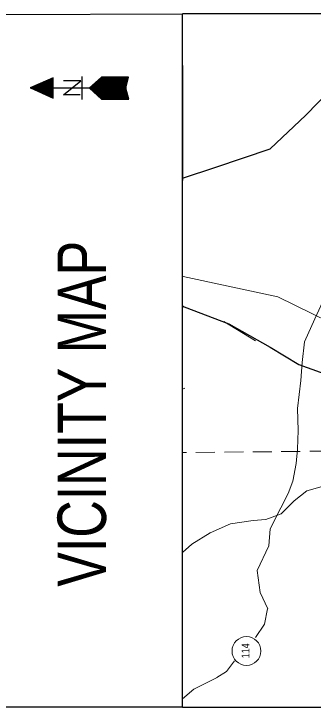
# Model space of a CAD drawing. Extents: x 2363323 to 2367082, y 6956018 to 6980837.
# Drawn here: x 2365644.7 to 2365838.7, y 6980386 to 6980835.5 of the extents above; entities that cross this region are included whole.
import ezdxf

# ---------------------------------------------------------------- set-up
doc = ezdxf.new("R2010")
doc.units = 0
doc.header["$LTSCALE"] = 4.1
doc.linetypes.add('MEDIUM_DASHED', pattern=[4.5, 3, -1.5])
doc.layers.add('62', color=7, linetype='Continuous', lineweight=13)
doc.layers.add('63', color=7, linetype='Continuous', lineweight=13)

msp = doc.modelspace()

# ---------------------------------------------------------------- linework, layer by layer
at = {"layer": '62', "lineweight": 25}
for p, q in [((2365753.976, 6980385.954), (2365753.974, 6980835.546)), ((2365688.99, 6980779.92), (2365688.99, 6980794.863)), ((2365655.17, 6980787.596), (2365717.68, 6980787.594))]:
    msp.add_line(p, q, dxfattribs=at)
at = {"layer": '62'}
for p, q in [((2365754.2, 6980727.402), (2365754.2, 6980802.018)), ((2365666.622, 6980782.485), (2365666.622, 6980792.566)), ((2365667.25, 6980782.192), (2365667.252, 6980792.836)), ((2365670.086, 6980792.859), (2365667.318, 6980792.859)), ((2365667.858, 6980781.902), (2365667.858, 6980793.108)), ((2365668.51, 6980781.63), (2365668.51, 6980793.399)), ((2365670.086, 6980793.512), (2365668.758, 6980793.512)), ((2365669.142, 6980781.338), (2365669.14, 6980793.67)), ((2365669.75, 6980781.045), (2365669.748, 6980793.939)), ((2365699.316, 6980782.282), (2365699.316, 6980792.522)), ((2365718.555, 6980792.859), (2365699.721, 6980792.859)), ((2365699.946, 6980781.72), (2365699.946, 6980793.084)), ((2365718.692, 6980793.512), (2365700.441, 6980793.512)), ((2365700.598, 6980781.136), (2365700.598, 6980793.622)), ((2365718.826, 6980794.119), (2365701.138, 6980794.119)), ((2365701.208, 6980780.595), (2365701.206, 6980794.186)), ((2365701.838, 6980780.258), (2365701.836, 6980794.503)), ((2365702.466, 6980780.258), (2365702.466, 6980794.503)), ((2365703.096, 6980780.258), (2365703.096, 6980794.502)), ((2365703.729, 6980780.258), (2365703.728, 6980794.502)), ((2365704.358, 6980780.258), (2365704.359, 6980794.502)), ((2365704.99, 6980780.258), (2365704.989, 6980794.503)), ((2365705.62, 6980780.258), (2365705.619, 6980794.502)), ((2365706.249, 6980780.258), (2365706.25, 6980794.502)), ((2365706.879, 6980780.256), (2365706.879, 6980794.502)), ((2365707.51, 6980780.256), (2365707.509, 6980794.5)), ((2365708.139, 6980780.259), (2365708.14, 6980794.502)), ((2365708.746, 6980780.259), (2365708.748, 6980794.502)), ((2365709.399, 6980780.258), (2365709.399, 6980794.503)), ((2365710.029, 6980780.258), (2365710.029, 6980794.502)), ((2365710.638, 6980780.259), (2365710.636, 6980794.503)), ((2365711.289, 6980780.258), (2365711.289, 6980794.502)), ((2365711.896, 6980780.258), (2365711.896, 6980794.503)), ((2365712.528, 6980780.258), (2365712.526, 6980794.502)), ((2365713.179, 6980780.258), (2365713.179, 6980794.502)), ((2365713.786, 6980780.258), (2365713.786, 6980794.502)), ((2365714.418, 6980780.258), (2365714.416, 6980794.502)), ((2365715.046, 6980780.259), (2365715.048, 6980794.502)), ((2365715.676, 6980780.258), (2365715.676, 6980794.503)), ((2365716.308, 6980780.258), (2365716.306, 6980794.502)), ((2365716.938, 6980780.258), (2365716.936, 6980794.502)), ((2365717.566, 6980788.336), (2365717.566, 6980794.502)), ((2365718.196, 6980791.24), (2365718.198, 6980794.503)), ((2365718.826, 6980794.096), (2365718.828, 6980794.502)), ((2365656.563, 6980787.1), (2365656.564, 6980788.134)), ((2365657.17, 6980786.806), (2365657.172, 6980788.426)), ((2365670.084, 6980788.472), (2365657.307, 6980788.472)), ((2365657.824, 6980786.514), (2365657.823, 6980788.698)), ((2365658.432, 6980786.22), (2365658.432, 6980788.965)), ((2365670.087, 6980789.08), (2365658.746, 6980789.079)), ((2365659.06, 6980785.95), (2365659.06, 6980789.238)), ((2365659.714, 6980785.658), (2365659.712, 6980789.506)), ((2365670.086, 6980789.732), (2365660.163, 6980789.732)), ((2365660.322, 6980785.365), (2365660.32, 6980789.776)), ((2365660.95, 6980785.072), (2365660.95, 6980790.069)), ((2365661.582, 6980784.78), (2365661.58, 6980790.339)), ((2365670.086, 6980790.362), (2365661.603, 6980790.362)), ((2365662.212, 6980784.488), (2365662.21, 6980790.632)), ((2365662.84, 6980784.218), (2365662.84, 6980790.902)), ((2365670.087, 6980790.968), (2365663.02, 6980790.97)), ((2365663.47, 6980783.926), (2365663.47, 6980791.194)), ((2365664.1, 6980783.634), (2365664.1, 6980791.464)), ((2365670.087, 6980791.622), (2365664.462, 6980791.622)), ((2365664.73, 6980783.362), (2365664.73, 6980791.734)), ((2365665.362, 6980783.048), (2365665.36, 6980792.004)), ((2365670.086, 6980792.229), (2365665.9, 6980792.23)), ((2365665.992, 6980782.755), (2365665.99, 6980792.274)), ((2365694.3, 6980786.829), (2365694.298, 6980788.089)), ((2365717.589, 6980788.472), (2365694.728, 6980788.472)), ((2365694.928, 6980786.265), (2365694.93, 6980788.652)), ((2365717.726, 6980789.079), (2365695.446, 6980789.079)), ((2365695.56, 6980785.704), (2365695.558, 6980789.192)), ((2365717.882, 6980789.733), (2365696.144, 6980789.732)), ((2365696.168, 6980785.14), (2365696.166, 6980789.754)), ((2365696.818, 6980784.555), (2365696.818, 6980790.294)), ((2365717.994, 6980790.363), (2365696.864, 6980790.362)), ((2365697.45, 6980783.994), (2365697.448, 6980790.856)), ((2365718.153, 6980790.969), (2365697.561, 6980790.969)), ((2365698.056, 6980783.43), (2365698.058, 6980791.42)), ((2365718.286, 6980791.62), (2365698.281, 6980791.622)), ((2365698.708, 6980782.868), (2365698.71, 6980791.959)), ((2365718.422, 6980792.229), (2365699.001, 6980792.229)), ((2365670.087, 6980787.842), (2365655.867, 6980787.842)), ((2365655.933, 6980787.392), (2365655.934, 6980787.864)), ((2365670.087, 6980787.212), (2365656.317, 6980787.212)), ((2365670.087, 6980786.583), (2365657.667, 6980786.582)), ((2365670.086, 6980785.95), (2365659.06, 6980785.95)), ((2365670.086, 6980785.32), (2365660.412, 6980785.32)), ((2365670.087, 6980784.69), (2365661.784, 6980784.69)), ((2365670.087, 6980784.06), (2365663.178, 6980784.06)), ((2365717.432, 6980787.212), (2365693.872, 6980787.212)), ((2365717.454, 6980787.842), (2365694.006, 6980787.842)), ((2365717.59, 6980786.583), (2365694.568, 6980786.583)), ((2365717.724, 6980785.95), (2365695.266, 6980785.948)), ((2365717.883, 6980785.322), (2365695.964, 6980785.32)), ((2365718.04, 6980784.69), (2365696.661, 6980784.69)), ((2365718.198, 6980784.06), (2365697.358, 6980784.06)), ((2365717.566, 6980780.256), (2365717.566, 6980786.649)), ((2365718.198, 6980780.258), (2365718.198, 6980784.06)), ((2365670.086, 6980783.43), (2365664.528, 6980783.43)), ((2365670.086, 6980782.802), (2365665.923, 6980782.8)), ((2365670.086, 6980782.17), (2365667.274, 6980782.172)), ((2365670.086, 6980781.54), (2365668.67, 6980781.542)), ((2365670.086, 6980780.932), (2365670.018, 6980780.932)), ((2365718.356, 6980783.43), (2365698.056, 6980783.43)), ((2365718.49, 6980782.8), (2365698.755, 6980782.8)), ((2365718.648, 6980782.17), (2365699.451, 6980782.168)), ((2365718.804, 6980781.542), (2365700.15, 6980781.54)), ((2365718.963, 6980780.932), (2365700.846, 6980780.932)), ((2365719.119, 6980780.282), (2365701.544, 6980780.28)), ((2365718.826, 6980780.259), (2365718.828, 6980781.472)), ((2365801.432, 6980623.464), (2365780.865, 6980636.09)), ((2365753.976, 6980592.164), (2365755.55, 6980592.862)), ((2365809.15, 6980449.68), (2365807.103, 6980439.848)), ((2365807.103, 6980439.848), (2365801.296, 6980431.162)), ((2365782.575, 6980408.974), (2365787.682, 6980416.04)), ((2365776.365, 6980405.082), (2365782.575, 6980408.974))]:
    msp.add_line(p, q, dxfattribs=at)
at = {"layer": '62', "linetype": 'MEDIUM_DASHED'}
msp.add_line((2365848.822, 6980551.996), (2365753.976, 6980551.008), dxfattribs=at)
at = {"layer": '62', "lineweight": 25}
for points in [[(2365753.976, 6980385.954), (2365634.174, 6980385.956), (2365634.172, 6980835.21), (2365753.974, 6980835.546)], [(2365753.976, 6980385.954), (2366219.249, 6980385.954), (2366219.249, 6980835.546), (2365753.974, 6980835.546)], [(2365655.46, 6980787.592), (2365670.086, 6980780.888), (2365670.086, 6980794.096), (2365655.326, 6980787.594)], [(2365693.692, 6980787.392), (2365701.568, 6980780.258), (2365719.119, 6980780.258), (2365717.364, 6980787.459), (2365718.916, 6980794.503), (2365701.568, 6980794.502), (2365693.736, 6980787.594)], [(2365753.976, 6980728.911), (2365775.622, 6980736.2), (2365810.86, 6980748.104), (2365833.947, 6980769.772), (2365857.058, 6980793.579), (2365861.646, 6980795.718)], [(2365687.752, 6980782.958), (2365676.75, 6980782.958), (2365688.156, 6980792.094), (2365676.748, 6980792.094)], [(2365753.974, 6980646.213), (2365755.146, 6980645.47), (2365784.062, 6980634.536), (2365810.86, 6980619.3), (2365829.356, 6980608.095), (2365860.208, 6980597.16)]]:
    msp.add_lwpolyline(points, dxfattribs=at)
at = {"layer": '62'}
for points in [[(2365809.287, 6980449.612), (2365804.356, 6980460.212), (2365802.512, 6980474.5), (2365809.894, 6980490.59), (2365810.838, 6980501.526), (2365817.837, 6980515.14), (2365822.54, 6980524.522), (2365825.554, 6980532.603), (2365827.714, 6980543.964), (2365828.59, 6980553.189), (2365829.04, 6980565.342), (2365828.5, 6980579.562), (2365830.796, 6980597.678), (2365831.606, 6980609.468), (2365833.203, 6980622.902), (2365839.778, 6980637.732), (2365846.368, 6980651.814), (2365853.028, 6980664.688), (2365864.278, 6980679.314), (2365871.414, 6980689.148), (2365878.929, 6980701.188), (2365885.793, 6980708.072)], [(2365871.414, 6980624.792), (2365815.923, 6980652.02), (2365754.402, 6980665.14)], [(2365753.974, 6980486.178), (2365760.05, 6980491.737), (2365771.955, 6980498.895), (2365785.095, 6980504.764), (2365799.742, 6980507.016), (2365808.048, 6980507.691), (2365817.97, 6980511.358), (2365826.498, 6980519.638), (2365834.6, 6980526.3), (2365844.567, 6980529.112), (2365856.966, 6980531.656)], [(2365753.976, 6980391.378), (2365761.377, 6980397.591), (2365776.545, 6980405.262)]]:
    msp.add_lwpolyline(points, dxfattribs=at)
msp.add_circle((2365795.467, 6980422.352), 9.364, dxfattribs=at)
at = {"layer": '63', "lineweight": 25}
for p, q in [((2365753.976, 6980385.954), (2365753.974, 6980835.546)), ((2365688.99, 6980779.92), (2365688.99, 6980794.863)), ((2365655.17, 6980787.596), (2365717.68, 6980787.594))]:
    msp.add_line(p, q, dxfattribs=at)
at = {"layer": '63'}
for p, q in [((2365754.2, 6980727.402), (2365754.2, 6980802.018)), ((2365666.622, 6980782.485), (2365666.622, 6980792.566)), ((2365667.25, 6980782.192), (2365667.252, 6980792.836)), ((2365670.086, 6980792.859), (2365667.318, 6980792.859)), ((2365667.858, 6980781.902), (2365667.858, 6980793.108)), ((2365668.51, 6980781.63), (2365668.51, 6980793.399)), ((2365670.086, 6980793.512), (2365668.758, 6980793.512)), ((2365669.142, 6980781.338), (2365669.14, 6980793.67)), ((2365669.75, 6980781.045), (2365669.748, 6980793.939)), ((2365699.316, 6980782.282), (2365699.316, 6980792.522)), ((2365718.555, 6980792.859), (2365699.721, 6980792.859)), ((2365699.946, 6980781.72), (2365699.946, 6980793.084)), ((2365718.692, 6980793.512), (2365700.441, 6980793.512)), ((2365700.598, 6980781.136), (2365700.598, 6980793.622)), ((2365718.826, 6980794.119), (2365701.138, 6980794.119)), ((2365701.208, 6980780.595), (2365701.206, 6980794.186)), ((2365701.838, 6980780.258), (2365701.836, 6980794.503)), ((2365702.466, 6980780.258), (2365702.466, 6980794.503)), ((2365703.096, 6980780.258), (2365703.096, 6980794.502)), ((2365703.729, 6980780.258), (2365703.728, 6980794.502)), ((2365704.358, 6980780.258), (2365704.359, 6980794.502)), ((2365704.99, 6980780.258), (2365704.989, 6980794.503)), ((2365705.62, 6980780.258), (2365705.619, 6980794.502)), ((2365706.249, 6980780.258), (2365706.25, 6980794.502)), ((2365706.879, 6980780.256), (2365706.879, 6980794.502)), ((2365707.51, 6980780.256), (2365707.509, 6980794.5)), ((2365708.139, 6980780.259), (2365708.14, 6980794.502)), ((2365708.746, 6980780.259), (2365708.748, 6980794.502)), ((2365709.399, 6980780.258), (2365709.399, 6980794.503)), ((2365710.029, 6980780.258), (2365710.029, 6980794.502)), ((2365710.638, 6980780.259), (2365710.636, 6980794.503)), ((2365711.289, 6980780.258), (2365711.289, 6980794.502)), ((2365711.896, 6980780.258), (2365711.896, 6980794.503)), ((2365712.528, 6980780.258), (2365712.526, 6980794.502)), ((2365713.179, 6980780.258), (2365713.179, 6980794.502)), ((2365713.786, 6980780.258), (2365713.786, 6980794.502)), ((2365714.418, 6980780.258), (2365714.416, 6980794.502)), ((2365715.046, 6980780.259), (2365715.048, 6980794.502)), ((2365715.676, 6980780.258), (2365715.676, 6980794.503)), ((2365716.308, 6980780.258), (2365716.306, 6980794.502)), ((2365716.938, 6980780.258), (2365716.936, 6980794.502)), ((2365717.566, 6980788.336), (2365717.566, 6980794.502)), ((2365718.196, 6980791.24), (2365718.198, 6980794.503)), ((2365718.826, 6980794.096), (2365718.828, 6980794.502)), ((2365656.563, 6980787.1), (2365656.564, 6980788.134)), ((2365657.17, 6980786.806), (2365657.172, 6980788.426)), ((2365670.084, 6980788.472), (2365657.307, 6980788.472)), ((2365657.824, 6980786.514), (2365657.823, 6980788.698)), ((2365658.432, 6980786.22), (2365658.432, 6980788.965)), ((2365670.087, 6980789.08), (2365658.746, 6980789.079)), ((2365659.06, 6980785.95), (2365659.06, 6980789.238)), ((2365659.714, 6980785.658), (2365659.712, 6980789.506)), ((2365670.086, 6980789.732), (2365660.163, 6980789.732)), ((2365660.322, 6980785.365), (2365660.32, 6980789.776)), ((2365660.95, 6980785.072), (2365660.95, 6980790.069)), ((2365661.582, 6980784.78), (2365661.58, 6980790.339)), ((2365670.086, 6980790.362), (2365661.603, 6980790.362)), ((2365662.212, 6980784.488), (2365662.21, 6980790.632)), ((2365662.84, 6980784.218), (2365662.84, 6980790.902)), ((2365670.087, 6980790.968), (2365663.02, 6980790.97)), ((2365663.47, 6980783.926), (2365663.47, 6980791.194)), ((2365664.1, 6980783.634), (2365664.1, 6980791.464)), ((2365670.087, 6980791.622), (2365664.462, 6980791.622)), ((2365664.73, 6980783.362), (2365664.73, 6980791.734)), ((2365665.362, 6980783.048), (2365665.36, 6980792.004)), ((2365670.086, 6980792.229), (2365665.9, 6980792.23)), ((2365665.992, 6980782.755), (2365665.99, 6980792.274)), ((2365694.3, 6980786.829), (2365694.298, 6980788.089)), ((2365717.589, 6980788.472), (2365694.728, 6980788.472)), ((2365694.928, 6980786.265), (2365694.93, 6980788.652)), ((2365717.726, 6980789.079), (2365695.446, 6980789.079)), ((2365695.56, 6980785.704), (2365695.558, 6980789.192)), ((2365717.882, 6980789.733), (2365696.144, 6980789.732)), ((2365696.168, 6980785.14), (2365696.166, 6980789.754)), ((2365696.818, 6980784.555), (2365696.818, 6980790.294)), ((2365717.994, 6980790.363), (2365696.864, 6980790.362)), ((2365697.45, 6980783.994), (2365697.448, 6980790.856)), ((2365718.153, 6980790.969), (2365697.561, 6980790.969)), ((2365698.056, 6980783.43), (2365698.058, 6980791.42)), ((2365718.286, 6980791.62), (2365698.281, 6980791.622)), ((2365698.708, 6980782.868), (2365698.71, 6980791.959)), ((2365718.422, 6980792.229), (2365699.001, 6980792.229)), ((2365670.087, 6980787.842), (2365655.867, 6980787.842)), ((2365655.933, 6980787.392), (2365655.934, 6980787.864)), ((2365670.087, 6980787.212), (2365656.317, 6980787.212)), ((2365670.087, 6980786.583), (2365657.667, 6980786.582)), ((2365670.086, 6980785.95), (2365659.06, 6980785.95)), ((2365670.086, 6980785.32), (2365660.412, 6980785.32)), ((2365670.087, 6980784.69), (2365661.784, 6980784.69)), ((2365670.087, 6980784.06), (2365663.178, 6980784.06)), ((2365717.432, 6980787.212), (2365693.872, 6980787.212)), ((2365717.454, 6980787.842), (2365694.006, 6980787.842)), ((2365717.59, 6980786.583), (2365694.568, 6980786.583)), ((2365717.724, 6980785.95), (2365695.266, 6980785.948)), ((2365717.883, 6980785.322), (2365695.964, 6980785.32)), ((2365718.04, 6980784.69), (2365696.661, 6980784.69)), ((2365718.198, 6980784.06), (2365697.358, 6980784.06)), ((2365717.566, 6980780.256), (2365717.566, 6980786.649)), ((2365718.198, 6980780.258), (2365718.198, 6980784.06)), ((2365670.086, 6980783.43), (2365664.528, 6980783.43)), ((2365670.086, 6980782.802), (2365665.923, 6980782.8)), ((2365670.086, 6980782.17), (2365667.274, 6980782.172)), ((2365670.086, 6980781.54), (2365668.67, 6980781.542)), ((2365670.086, 6980780.932), (2365670.018, 6980780.932)), ((2365718.356, 6980783.43), (2365698.056, 6980783.43)), ((2365718.49, 6980782.8), (2365698.755, 6980782.8)), ((2365718.648, 6980782.17), (2365699.451, 6980782.168)), ((2365718.804, 6980781.542), (2365700.15, 6980781.54)), ((2365718.963, 6980780.932), (2365700.846, 6980780.932)), ((2365719.119, 6980780.282), (2365701.544, 6980780.28)), ((2365718.826, 6980780.259), (2365718.828, 6980781.472)), ((2365801.432, 6980623.464), (2365780.865, 6980636.09)), ((2365753.976, 6980592.164), (2365755.55, 6980592.862)), ((2365809.15, 6980449.68), (2365807.103, 6980439.848)), ((2365807.103, 6980439.848), (2365801.296, 6980431.162)), ((2365782.575, 6980408.974), (2365787.682, 6980416.04)), ((2365776.365, 6980405.082), (2365782.575, 6980408.974))]:
    msp.add_line(p, q, dxfattribs=at)
at = {"layer": '63', "linetype": 'MEDIUM_DASHED'}
msp.add_line((2365848.822, 6980551.996), (2365753.976, 6980551.008), dxfattribs=at)
at = {"layer": '63', "lineweight": 25}
for points in [[(2365753.976, 6980385.954), (2365634.174, 6980385.956), (2365634.172, 6980835.21), (2365753.974, 6980835.546)], [(2365753.976, 6980385.954), (2366219.249, 6980385.954), (2366219.249, 6980835.546), (2365753.974, 6980835.546)], [(2365655.46, 6980787.592), (2365670.086, 6980780.888), (2365670.086, 6980794.096), (2365655.326, 6980787.594)], [(2365693.692, 6980787.392), (2365701.568, 6980780.258), (2365719.119, 6980780.258), (2365717.364, 6980787.459), (2365718.916, 6980794.503), (2365701.568, 6980794.502), (2365693.736, 6980787.594)], [(2365753.976, 6980728.911), (2365775.622, 6980736.2), (2365810.86, 6980748.104), (2365833.947, 6980769.772), (2365857.058, 6980793.579), (2365861.646, 6980795.718)], [(2365687.752, 6980782.958), (2365676.75, 6980782.958), (2365688.156, 6980792.094), (2365676.748, 6980792.094)], [(2365753.974, 6980646.213), (2365755.146, 6980645.47), (2365784.062, 6980634.536), (2365810.86, 6980619.3), (2365829.356, 6980608.095), (2365860.208, 6980597.16)]]:
    msp.add_lwpolyline(points, dxfattribs=at)
at = {"layer": '63'}
for points in [[(2365809.287, 6980449.612), (2365804.356, 6980460.212), (2365802.512, 6980474.5), (2365809.894, 6980490.59), (2365810.838, 6980501.526), (2365817.837, 6980515.14), (2365822.54, 6980524.522), (2365825.554, 6980532.603), (2365827.714, 6980543.964), (2365828.59, 6980553.189), (2365829.04, 6980565.342), (2365828.5, 6980579.562), (2365830.796, 6980597.678), (2365831.606, 6980609.468), (2365833.203, 6980622.902), (2365839.778, 6980637.732), (2365846.368, 6980651.814), (2365853.028, 6980664.688), (2365864.278, 6980679.314), (2365871.414, 6980689.148), (2365878.929, 6980701.188), (2365885.793, 6980708.072)], [(2365871.414, 6980624.792), (2365815.923, 6980652.02), (2365754.402, 6980665.14)], [(2365753.974, 6980486.178), (2365760.05, 6980491.737), (2365771.955, 6980498.895), (2365785.095, 6980504.764), (2365799.742, 6980507.016), (2365808.048, 6980507.691), (2365817.97, 6980511.358), (2365826.498, 6980519.638), (2365834.6, 6980526.3), (2365844.567, 6980529.112), (2365856.966, 6980531.656)], [(2365753.976, 6980391.378), (2365761.377, 6980397.591), (2365776.545, 6980405.262)]]:
    msp.add_lwpolyline(points, dxfattribs=at)
msp.add_circle((2365795.467, 6980422.352), 9.364, dxfattribs=at)

# ---------------------------------------------------------------- texts
at = {"layer": '62'}
for s, height, width, p in [('VICINITY MAP', 31.45, 0.8, (2365704.424, 6980464.038)), ('114', 5.099, 0.85, (2365797.424, 6980417.661))]:
    msp.add_text(s, height=height, rotation=90, dxfattribs=dict(at, width=width)).set_placement(p)
at = {"layer": '63'}
for s, height, width, p in [('VICINITY MAP', 31.45, 0.8, (2365704.424, 6980464.038)), ('114', 5.099, 0.85, (2365797.424, 6980417.661))]:
    msp.add_text(s, height=height, rotation=90, dxfattribs=dict(at, width=width)).set_placement(p)

doc.saveas('drawing.dxf')
